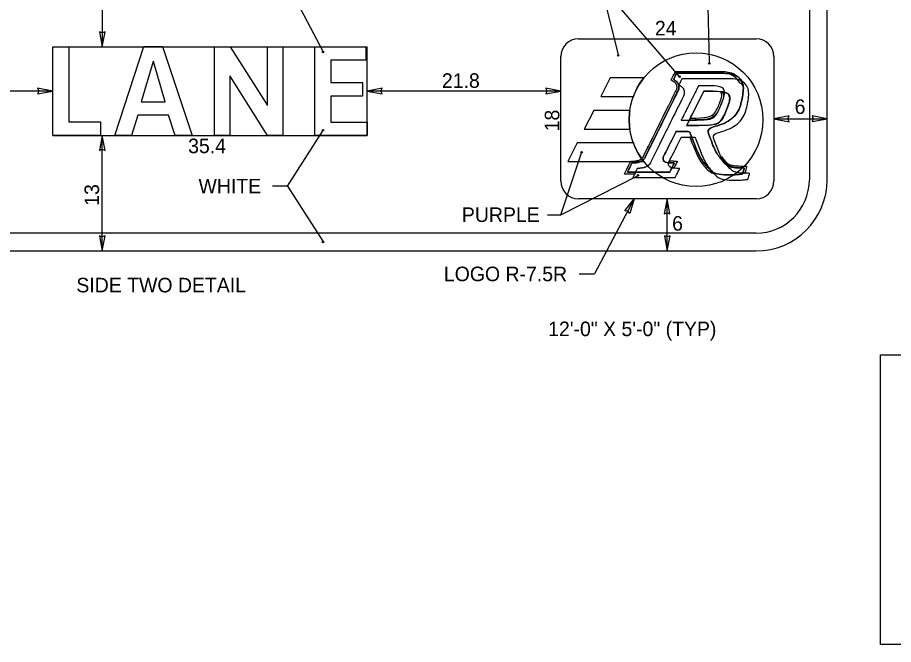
# Model space of a CAD drawing. Extents: x 319706 to 320346, y 1621790 to 1622121.
# Drawn here: x 319772.1 to 319856.4, y 1621813.2 to 1621873.6 of the extents above; entities that cross this region are included whole.
import ezdxf

# ---------------------------------------------------------------- set-up
doc = ezdxf.new("R2010")
doc.units = 0
for name, color, linetype in [('1', 7, 'Continuous'), ('52', 7, 'Continuous'), ('SignPanel', 7, 'Continuous'), ('SOILS_SP83_SHP', 7, 'Continuous'), ('TextAlert', 7, 'Continuous')]:
    doc.layers.add(name, color=color, linetype=linetype)

msp = doc.modelspace()

# ---------------------------------------------------------------- linework, layer by layer
at = {"layer": '1'}
for p, q in [((319798.08, 1621876.744), (319801.479, 1621870.318)), ((319828.244, 1621876.645), (319829.899, 1621869.995)), ((319835.764, 1621867.926), (319828.244, 1621876.645)), ((319838.529, 1621874.588), (319838.662, 1621869.215)), ((319844.895, 1621863.82), (319850.025, 1621863.82)), ((319798.08, 1621857.34), (319801.479, 1621862.649)), ((319824.375, 1621854.589), (319826.382, 1621860.527)), ((319824.375, 1621854.589), (319831.762, 1621858.332)), ((319798.08, 1621857.34), (319796.638, 1621857.34)), ((319798.08, 1621857.34), (319801.479, 1621852.03)), ((319831.44, 1621856.125), (319827.629, 1621848.888)), ((319834.613, 1621851.105), (319834.613, 1621856.125)), ((319823.092, 1621854.589), (319824.375, 1621854.589)), ((319826.132, 1621848.888), (319827.629, 1621848.888))]:
    msp.add_line(p, q, dxfattribs=at)
for centre, major_axis, ratio in [((319801.479, 1621870.248), (0.0736, 0), 0.961364), ((319829.899, 1621869.924), (0, 0.0707), 0.906668), ((319838.662, 1621869.144), (0, 0.0707), 0.906668), ((319835.811, 1621867.877), (0, 0.0707), 0.906668), ((319801.479, 1621862.72), (0.0736, 0), 0.960359), ((319826.382, 1621860.598), (0, 0.0707), 0.906668), ((319831.809, 1621858.381), (0, 0.0707), 0.906668), ((319801.479, 1621851.96), (0.0736, 0), 0.961364)]:
    msp.add_ellipse(centre, major_axis=major_axis, ratio=ratio, dxfattribs=at)
at = {"layer": '52'}
for p, q in [((319780.238, 1621872.088), (319779.968, 1621872.198)), ((319779.968, 1621872.198), (319780.238, 1621870.748)), ((319780.238, 1621870.748), (319780.518, 1621872.198)), ((319780.518, 1621872.198), (319780.238, 1621872.088)), ((319775.465, 1621866.484), (319774.015, 1621866.764)), ((319774.015, 1621866.764), (319774.125, 1621866.484)), ((319807.173, 1621866.754), (319805.723, 1621866.484)), ((319807.063, 1621866.484), (319807.173, 1621866.754)), ((319824.375, 1621866.484), (319822.925, 1621866.764)), ((319822.925, 1621866.764), (319823.035, 1621866.484)), ((319774.125, 1621866.484), (319774.015, 1621866.214)), ((319774.015, 1621866.214), (319775.465, 1621866.484)), ((319805.723, 1621866.484), (319807.173, 1621866.204)), ((319807.173, 1621866.204), (319807.063, 1621866.484)), ((319823.035, 1621866.484), (319822.925, 1621866.214)), ((319822.925, 1621866.214), (319824.375, 1621866.484)), ((319846.345, 1621864.09), (319844.895, 1621863.82)), ((319844.895, 1621863.82), (319846.345, 1621863.54)), ((319846.235, 1621863.82), (319846.345, 1621864.09)), ((319846.345, 1621863.54), (319846.235, 1621863.82)), ((319850.025, 1621863.82), (319848.575, 1621864.1)), ((319848.575, 1621864.1), (319848.685, 1621863.82)), ((319848.685, 1621863.82), (319848.575, 1621863.55)), ((319848.575, 1621863.55), (319850.025, 1621863.82)), ((319780.238, 1621862.22), (319779.958, 1621860.77)), ((319780.508, 1621860.77), (319780.238, 1621862.22)), ((319779.958, 1621860.77), (319780.238, 1621860.88)), ((319780.238, 1621860.88), (319780.508, 1621860.77)), ((319830.526, 1621854.968), (319831.44, 1621856.125)), ((319831.44, 1621856.125), (319831.012, 1621854.712)), ((319834.613, 1621856.125), (319834.333, 1621854.675)), ((319834.883, 1621854.675), (319834.613, 1621856.125)), ((319830.816, 1621854.94), (319830.526, 1621854.968)), ((319831.012, 1621854.712), (319830.816, 1621854.94)), ((319834.333, 1621854.675), (319834.613, 1621854.785)), ((319834.613, 1621854.785), (319834.883, 1621854.675)), ((319780.238, 1621852.445), (319779.968, 1621852.555)), ((319779.968, 1621852.555), (319780.238, 1621851.105)), ((319780.238, 1621851.105), (319780.518, 1621852.555)), ((319780.518, 1621852.555), (319780.238, 1621852.445)), ((319834.613, 1621852.445), (319834.343, 1621852.555)), ((319834.343, 1621852.555), (319834.613, 1621851.105)), ((319834.613, 1621851.105), (319834.893, 1621852.555)), ((319834.893, 1621852.555), (319834.613, 1621852.445))]:
    msp.add_line(p, q, dxfattribs=at)
at = {"layer": 'SignPanel'}
for p, q in [((319848.304, 1621895.565), (319848.304, 1621857.945)), ((319850.014, 1621857.945), (319850.014, 1621895.565)), ((319780.238, 1621882.74), (319780.238, 1621870.748)), ((319826.065, 1621871.514), (319843.183, 1621871.514)), ((319824.375, 1621857.834), (319824.375, 1621869.805)), ((319844.895, 1621869.805), (319844.895, 1621857.834)), ((319775.465, 1621866.484), (319756.605, 1621866.484)), ((319824.375, 1621866.484), (319805.723, 1621866.484)), ((319834.758, 1621865.095), (319834.765, 1621865.11)), ((319834.925, 1621865.03), (319834.918, 1621865.015)), ((319780.238, 1621851.105), (319780.238, 1621862.22)), ((319836.975, 1621862.064), (319836.783, 1621862.064)), ((319831.564, 1621858.674), (319831.474, 1621858.496)), ((319843.183, 1621856.125), (319826.086, 1621856.125)), ((319843.174, 1621852.815), (319733.75, 1621852.815)), ((319733.75, 1621851.105), (319843.174, 1621851.105))]:
    msp.add_line(p, q, dxfattribs=at)
for points in [[(319775.465, 1621862.22), (319775.465, 1621870.748), (319777.011, 1621870.748), (319777.011, 1621863.524), (319780.059, 1621863.524), (319780.059, 1621862.22), (319775.465, 1621862.22)], [(319787.245, 1621862.22), (319786.623, 1621864.169), (319783.673, 1621864.169), (319783.051, 1621862.22), (319781.448, 1621862.22), (319784.244, 1621870.77), (319786.043, 1621870.77), (319788.899, 1621862.22), (319787.245, 1621862.22)], [(319796.151, 1621862.22), (319792.539, 1621867.933), (319792.517, 1621867.933), (319792.517, 1621862.22), (319791.052, 1621862.22), (319791.052, 1621870.748), (319792.539, 1621870.748), (319796.137, 1621865.094), (319796.147, 1621865.094), (319796.151, 1621870.748), (319797.624, 1621870.748), (319797.624, 1621862.22), (319796.151, 1621862.22)], [(319800.714, 1621862.22), (319800.714, 1621870.748), (319805.6, 1621870.748), (319805.6, 1621869.444), (319802.245, 1621869.444), (319802.245, 1621867.297), (319805.278, 1621867.297), (319805.278, 1621865.985), (319802.245, 1621865.985), (319802.245, 1621863.502), (319805.723, 1621863.502), (319805.723, 1621862.22), (319800.714, 1621862.22)], [(319785.165, 1621869.319), (319785.122, 1621869.321), (319783.98, 1621865.451), (319786.307, 1621865.451), (319785.165, 1621869.319)], [(319832.371, 1621867.754), (319829.143, 1621867.754), (319828.232, 1621865.965), (319831.359, 1621865.965)], [(319839.009, 1621866.47), (319838.153, 1621866.47), (319836.491, 1621863.177), (319837.036, 1621863.177)], [(319831.021, 1621864.623), (319827.548, 1621864.623), (319826.636, 1621862.834), (319831.021, 1621862.834)], [(319831.359, 1621861.493), (319825.953, 1621861.493), (319825.042, 1621859.704), (319832.372, 1621859.704)]]:
    msp.add_lwpolyline(points, dxfattribs=at)
msp.add_circle((319837.397, 1621863.729), 6.438, dxfattribs=at)
for centre, radius, start, end in [((319826.084, 1621869.804), 1.71, 90.65967, 180), ((319843.183, 1621869.804), 1.71, 0, 90), ((319837.397, 1621863.729), 6.438, 141.30928, 159.68118), ((319840.633, 1621865.787), 1.786, 44.17508, 57.10952), ((319837.397, 1621863.729), 6.438, 172.01482, 187.98741), ((319837.397, 1621863.729), 6.438, 200.32564, 218.69891), ((319845.493, 1621863.128), 6.357, 207.70861, 215.03564), ((319835.295, 1621859.594), 0.486, 153.95162, 176.84356), ((319835.563, 1621860.105), 1.029, 244.34447, 254.36684), ((319841.02, 1621860.665), 2.825, 217.43245, 229.81517), ((319842.449, 1621863.158), 4.583, 263.2057, 265.47819), ((319826.084, 1621857.835), 1.71, 180, 270), ((319843.174, 1621857.945), 6.84, 270, 0), ((319843.174, 1621857.945), 5.13, 270, 0), ((319843.183, 1621857.835), 1.71, 270, 360)]:
    msp.add_arc(centre, radius, start, end, dxfattribs=at)
for points, degree in [([(319834.765, 1621865.11), (319835.228, 1621866.043), (319835.557, 1621866.705), (319835.557, 1621866.705), (319835.557, 1621866.705), (319835.564, 1621866.76), (319835.564, 1621866.76), (319835.564, 1621866.76), (319835.564, 1621866.839), (319835.564, 1621866.839), (319835.564, 1621866.839), (319835.564, 1621866.899), (319835.564, 1621866.899), (319835.564, 1621866.899), (319835.559, 1621866.963), (319835.559, 1621866.963), (319835.559, 1621866.963), (319835.541, 1621867.04), (319835.541, 1621867.04), (319835.541, 1621867.04), (319835.509, 1621867.123), (319835.509, 1621867.123), (319835.509, 1621867.123), (319835.479, 1621867.173), (319835.479, 1621867.173), (319835.479, 1621867.173), (319835.419, 1621867.252), (319835.419, 1621867.252), (319835.419, 1621867.252), (319835.331, 1621867.325), (319835.331, 1621867.325), (319835.331, 1621867.325), (319835.234, 1621867.396), (319835.234, 1621867.396), (319835.234, 1621867.396), (319834.99, 1621867.544), (319834.99, 1621867.544), (319834.99, 1621867.544), (319835.41, 1621868.375), (319835.41, 1621868.375), (319835.41, 1621868.375), (319839.531, 1621868.375), (319839.531, 1621868.375), (319840.818, 1621868.375), (319841.612, 1621867.814), (319841.914, 1621867.032)], 3), ([(319835.461, 1621862.583), (319835.461, 1621862.583), (319834.368, 1621860.376), (319834.368, 1621860.376), (319834.17, 1621860.054), (319834.313, 1621859.567), (319835.312, 1621859.567), (319835.312, 1621859.567), (319834.866, 1621858.674), (319834.866, 1621858.674), (319834.866, 1621858.674), (319830.786, 1621858.674), (319830.786, 1621858.674), (319830.786, 1621858.674), (319831.232, 1621859.567), (319831.232, 1621859.567), (319831.232, 1621859.567), (319831.359, 1621859.567), (319831.359, 1621859.567), (319831.359, 1621859.567), (319831.497, 1621859.573), (319831.497, 1621859.573), (319831.497, 1621859.573), (319831.612, 1621859.585), (319831.612, 1621859.585), (319831.612, 1621859.585), (319831.811, 1621859.627), (319831.811, 1621859.627), (319831.811, 1621859.627), (319831.962, 1621859.669), (319831.962, 1621859.669), (319831.962, 1621859.669), (319832.088, 1621859.724), (319832.088, 1621859.724), (319832.088, 1621859.724), (319832.179, 1621859.772), (319832.179, 1621859.772), (319832.179, 1621859.772), (319832.269, 1621859.826), (319832.269, 1621859.826), (319832.269, 1621859.826), (319832.36, 1621859.911), (319832.36, 1621859.911), (319832.36, 1621859.911), (319832.426, 1621859.995), (319832.426, 1621859.995), (319832.426, 1621859.995), (319832.45, 1621860.043), (319832.45, 1621860.043), (319832.45, 1621860.043), (319835.731, 1621866.653), (319835.731, 1621866.653), (319835.731, 1621866.653), (319835.743, 1621866.749), (319835.743, 1621866.749), (319835.743, 1621866.749), (319835.743, 1621866.839), (319835.743, 1621866.839), (319835.743, 1621866.839), (319835.743, 1621866.906), (319835.743, 1621866.906), (319835.743, 1621866.906), (319835.737, 1621866.99), (319835.737, 1621866.99), (319835.737, 1621866.99), (319835.712, 1621867.093), (319835.712, 1621867.093), (319835.712, 1621867.093), (319835.67, 1621867.201), (319835.67, 1621867.201), (319835.67, 1621867.201), (319835.628, 1621867.273), (319835.628, 1621867.273), (319835.628, 1621867.273), (319835.549, 1621867.376), (319835.549, 1621867.376), (319835.549, 1621867.376), (319835.441, 1621867.467), (319835.441, 1621867.467), (319835.441, 1621867.467), (319835.333, 1621867.545), (319835.333, 1621867.545), (319835.333, 1621867.545), (319835.224, 1621867.611), (319835.224, 1621867.611), (319835.224, 1621867.611), (319835.52, 1621868.196), (319835.52, 1621868.196), (319835.52, 1621868.196), (319839.531, 1621868.196), (319839.531, 1621868.196), (319841.352, 1621868.196), (319842.082, 1621867.092), (319841.827, 1621865.8), (319841.544, 1621864.369), (319840.171, 1621863.249), (319838.302, 1621862.922), (319838.711, 1621862.159), (319839.2, 1621860.697), (319839.899, 1621859.826), (319840.374, 1621859.234), (319841.201, 1621859.09), (319842.045, 1621859.09), (319842.045, 1621859.09), (319841.882, 1621858.519), (319841.882, 1621858.519), (319841.882, 1621858.519), (319841.77, 1621858.503), (319841.77, 1621858.503), (319841.306, 1621858.441), (319841.008, 1621858.425), (319840.665, 1621858.425), (319839.529, 1621858.425), (319838.831, 1621858.752), (319838.295, 1621859.421), (319837.67, 1621860.199), (319837.067, 1621861.856), (319836.766, 1621862.583), (319836.766, 1621862.583), (319835.461, 1621862.583), (319835.461, 1621862.583)], 3), ([(319835.98, 1621862.064), (319835.98, 1621862.064), (319834.887, 1621859.858), (319834.887, 1621859.858), (319834.688, 1621859.536), (319834.831, 1621859.048), (319835.831, 1621859.048), (319835.831, 1621859.048), (319835.385, 1621858.156), (319835.385, 1621858.156), (319835.385, 1621858.156), (319831.304, 1621858.156), (319831.304, 1621858.156), (319831.304, 1621858.156), (319831.751, 1621859.048), (319831.751, 1621859.048), (319831.751, 1621859.048), (319831.877, 1621859.048), (319831.877, 1621859.048), (319831.877, 1621859.048), (319832.016, 1621859.055), (319832.016, 1621859.055), (319832.016, 1621859.055), (319832.13, 1621859.066), (319832.13, 1621859.066), (319832.13, 1621859.066), (319832.33, 1621859.108), (319832.33, 1621859.108), (319832.33, 1621859.108), (319832.48, 1621859.151), (319832.48, 1621859.151), (319832.48, 1621859.151), (319832.607, 1621859.205), (319832.607, 1621859.205), (319832.607, 1621859.205), (319832.697, 1621859.253), (319832.697, 1621859.253), (319832.697, 1621859.253), (319832.788, 1621859.308), (319832.788, 1621859.308), (319832.788, 1621859.308), (319832.878, 1621859.392), (319832.878, 1621859.392), (319832.878, 1621859.392), (319832.945, 1621859.476), (319832.945, 1621859.476), (319832.945, 1621859.476), (319832.968, 1621859.525), (319832.968, 1621859.525), (319832.968, 1621859.525), (319836.249, 1621866.134), (319836.249, 1621866.134), (319836.249, 1621866.134), (319836.261, 1621866.23), (319836.261, 1621866.23), (319836.261, 1621866.23), (319836.261, 1621866.32), (319836.261, 1621866.32), (319836.261, 1621866.32), (319836.261, 1621866.387), (319836.261, 1621866.387), (319836.261, 1621866.387), (319836.255, 1621866.471), (319836.255, 1621866.471), (319836.255, 1621866.471), (319836.231, 1621866.574), (319836.231, 1621866.574), (319836.231, 1621866.574), (319836.189, 1621866.683), (319836.189, 1621866.683), (319836.189, 1621866.683), (319836.147, 1621866.755), (319836.147, 1621866.755), (319836.147, 1621866.755), (319836.068, 1621866.858), (319836.068, 1621866.858), (319836.068, 1621866.858), (319835.96, 1621866.948), (319835.96, 1621866.948), (319835.96, 1621866.948), (319835.851, 1621867.026), (319835.851, 1621867.026), (319835.851, 1621867.026), (319835.743, 1621867.092), (319835.743, 1621867.092), (319835.743, 1621867.092), (319836.038, 1621867.678), (319836.038, 1621867.678), (319836.038, 1621867.678), (319840.05, 1621867.678), (319840.05, 1621867.678), (319841.87, 1621867.678), (319842.601, 1621866.573), (319842.346, 1621865.281), (319842.063, 1621863.85), (319840.69, 1621862.73), (319838.821, 1621862.403), (319839.23, 1621861.641), (319839.719, 1621860.178), (319840.418, 1621859.307), (319840.893, 1621858.716), (319841.72, 1621858.571), (319842.564, 1621858.571), (319842.564, 1621858.571), (319842.4, 1621858), (319842.4, 1621858), (319842.4, 1621858), (319842.288, 1621857.984), (319842.288, 1621857.984), (319841.825, 1621857.922), (319841.526, 1621857.907), (319841.184, 1621857.907), (319840.048, 1621857.907), (319839.35, 1621858.233), (319838.813, 1621858.902), (319838.189, 1621859.68), (319837.586, 1621861.338), (319837.285, 1621862.064), (319837.285, 1621862.064), (319835.98, 1621862.064), (319835.98, 1621862.064)], 3), ([(319834.925, 1621865.03), (319835.388, 1621865.963), (319835.731, 1621866.653), (319835.731, 1621866.653), (319835.731, 1621866.653), (319835.743, 1621866.749), (319835.743, 1621866.749), (319835.743, 1621866.749), (319835.743, 1621866.839), (319835.743, 1621866.839), (319835.743, 1621866.839), (319835.743, 1621866.906), (319835.743, 1621866.906), (319835.743, 1621866.906), (319835.737, 1621866.99), (319835.737, 1621866.99), (319835.737, 1621866.99), (319835.712, 1621867.093), (319835.712, 1621867.093), (319835.712, 1621867.093), (319835.67, 1621867.201), (319835.67, 1621867.201), (319835.67, 1621867.201), (319835.628, 1621867.273), (319835.628, 1621867.273), (319835.628, 1621867.273), (319835.549, 1621867.376), (319835.549, 1621867.376), (319835.549, 1621867.376), (319835.441, 1621867.467), (319835.441, 1621867.467), (319835.441, 1621867.467), (319835.333, 1621867.545), (319835.333, 1621867.545), (319835.333, 1621867.545), (319835.224, 1621867.611), (319835.224, 1621867.611), (319835.224, 1621867.611), (319835.52, 1621868.196), (319835.52, 1621868.196), (319835.52, 1621868.196), (319839.531, 1621868.196), (319839.531, 1621868.196), (319841.352, 1621868.196), (319842.082, 1621867.092), (319841.827, 1621865.8), (319841.544, 1621864.369), (319840.171, 1621863.249), (319838.302, 1621862.922), (319838.711, 1621862.159), (319839.2, 1621860.697), (319839.899, 1621859.826), (319840.374, 1621859.234), (319841.201, 1621859.09), (319842.045, 1621859.09), (319842.045, 1621859.09), (319841.882, 1621858.519), (319841.882, 1621858.519), (319841.882, 1621858.519), (319841.77, 1621858.503), (319841.77, 1621858.503), (319841.306, 1621858.441), (319841.008, 1621858.425), (319840.665, 1621858.425), (319839.529, 1621858.425), (319838.831, 1621858.752), (319838.295, 1621859.421), (319837.67, 1621860.199), (319837.067, 1621861.856), (319836.766, 1621862.583), (319836.766, 1621862.583), (319835.461, 1621862.583), (319835.461, 1621862.583)], 3), ([(319841.603, 1621867.287), (319841.254, 1621867.836), (319840.57, 1621868.196), (319839.531, 1621868.196), (319839.531, 1621868.196), (319835.52, 1621868.196), (319835.52, 1621868.196), (319835.52, 1621868.196), (319835.224, 1621867.611), (319835.224, 1621867.611), (319835.224, 1621867.611), (319835.333, 1621867.545), (319835.333, 1621867.545), (319835.333, 1621867.545), (319835.441, 1621867.467), (319835.441, 1621867.467), (319835.441, 1621867.467), (319835.549, 1621867.376), (319835.549, 1621867.376), (319835.549, 1621867.376), (319835.628, 1621867.273), (319835.628, 1621867.273), (319835.628, 1621867.273), (319835.67, 1621867.201), (319835.67, 1621867.201), (319835.67, 1621867.201), (319835.712, 1621867.093), (319835.712, 1621867.093), (319835.712, 1621867.093), (319835.737, 1621866.99), (319835.737, 1621866.99), (319835.737, 1621866.99), (319835.743, 1621866.906), (319835.743, 1621866.906), (319835.743, 1621866.906), (319835.743, 1621866.839), (319835.743, 1621866.839), (319835.743, 1621866.839), (319835.743, 1621866.749), (319835.743, 1621866.749), (319835.743, 1621866.749), (319835.731, 1621866.653), (319835.731, 1621866.653), (319835.731, 1621866.653), (319835.388, 1621865.963), (319834.925, 1621865.03)], 3), ([(319836.294, 1621864.332), (319836.104, 1621863.957), (319835.972, 1621863.696), (319835.972, 1621863.696), (319835.972, 1621863.696), (319836.517, 1621863.696), (319836.517, 1621863.696), (319838.306, 1621863.696), (319839.272, 1621863.828), (319839.873, 1621865.384), (319840.29, 1621866.462), (319839.828, 1621866.988), (319838.49, 1621866.988), (319838.49, 1621866.988), (319837.634, 1621866.988), (319837.634, 1621866.988)], 3), ([(319837.634, 1621866.988), (319837.634, 1621866.988), (319836.785, 1621865.307), (319836.301, 1621864.347)], 2), ([(319838.153, 1621866.47), (319838.153, 1621866.47), (319836.491, 1621863.177), (319836.491, 1621863.177), (319836.491, 1621863.177), (319837.036, 1621863.177), (319837.036, 1621863.177), (319838.825, 1621863.177), (319839.79, 1621863.309), (319840.392, 1621864.865), (319840.809, 1621865.943), (319840.347, 1621866.47), (319839.009, 1621866.47), (319839.009, 1621866.47), (319838.153, 1621866.47), (319838.153, 1621866.47)], 3), ([(319839.985, 1621866.323), (319840.058, 1621866.079), (319840.021, 1621865.766), (319839.873, 1621865.384), (319839.299, 1621863.898), (319838.392, 1621863.711), (319836.753, 1621863.697)], 3), ([(319836.844, 1621863.877), (319838.401, 1621863.895), (319839.179, 1621864.083), (319839.706, 1621865.448), (319839.867, 1621865.863), (319839.898, 1621866.171), (319839.786, 1621866.388)], 3), ([(319837.036, 1621863.177), (319838.825, 1621863.177), (319839.79, 1621863.309), (319840.392, 1621864.865), (319840.809, 1621865.943), (319840.347, 1621866.47), (319839.009, 1621866.47)], 3), ([(319839.786, 1621866.388), (319839.857, 1621866.369), (319839.924, 1621866.348), (319839.985, 1621866.323)], 2), ([(319831.474, 1621858.496), (319830.904, 1621858.496), (319830.496, 1621858.496), (319830.496, 1621858.496), (319830.496, 1621858.496), (319831.121, 1621859.746), (319831.121, 1621859.746), (319831.121, 1621859.746), (319831.355, 1621859.746), (319831.355, 1621859.746), (319831.355, 1621859.746), (319831.484, 1621859.752), (319831.484, 1621859.752), (319831.484, 1621859.752), (319831.584, 1621859.762), (319831.584, 1621859.762), (319831.584, 1621859.762), (319831.768, 1621859.801), (319831.768, 1621859.801), (319831.768, 1621859.801), (319831.902, 1621859.838), (319831.902, 1621859.838), (319831.902, 1621859.838), (319832.01, 1621859.885), (319832.01, 1621859.885), (319832.01, 1621859.885), (319832.091, 1621859.928), (319832.091, 1621859.928), (319832.091, 1621859.928), (319832.161, 1621859.97), (319832.161, 1621859.97), (319832.161, 1621859.97), (319832.228, 1621860.032), (319832.228, 1621860.032), (319832.228, 1621860.032), (319832.274, 1621860.091), (319832.274, 1621860.091), (319832.274, 1621860.091), (319832.289, 1621860.122), (319832.289, 1621860.122), (319832.289, 1621860.122), (319833.786, 1621863.137), (319834.758, 1621865.095)], 3), ([(319835.461, 1621862.583), (319835.461, 1621862.583), (319834.368, 1621860.376), (319834.368, 1621860.376), (319834.17, 1621860.054), (319834.313, 1621859.567), (319835.312, 1621859.567), (319835.312, 1621859.567), (319834.866, 1621858.674), (319834.866, 1621858.674), (319834.866, 1621858.674), (319830.786, 1621858.674), (319830.786, 1621858.674), (319830.786, 1621858.674), (319831.232, 1621859.567), (319831.232, 1621859.567), (319831.232, 1621859.567), (319831.359, 1621859.567), (319831.359, 1621859.567), (319831.359, 1621859.567), (319831.497, 1621859.573), (319831.497, 1621859.573), (319831.497, 1621859.573), (319831.612, 1621859.585), (319831.612, 1621859.585), (319831.612, 1621859.585), (319831.811, 1621859.627), (319831.811, 1621859.627), (319831.811, 1621859.627), (319831.962, 1621859.669), (319831.962, 1621859.669), (319831.962, 1621859.669), (319832.088, 1621859.724), (319832.088, 1621859.724), (319832.088, 1621859.724), (319832.179, 1621859.772), (319832.179, 1621859.772), (319832.179, 1621859.772), (319832.269, 1621859.826), (319832.269, 1621859.826), (319832.269, 1621859.826), (319832.36, 1621859.911), (319832.36, 1621859.911), (319832.36, 1621859.911), (319832.426, 1621859.995), (319832.426, 1621859.995), (319832.426, 1621859.995), (319832.45, 1621860.043), (319832.45, 1621860.043), (319832.45, 1621860.043), (319833.946, 1621863.058), (319834.918, 1621865.015)], 3), ([(319834.918, 1621865.015), (319833.946, 1621863.058), (319832.45, 1621860.043), (319832.45, 1621860.043), (319832.45, 1621860.043), (319832.426, 1621859.995), (319832.426, 1621859.995), (319832.426, 1621859.995), (319832.36, 1621859.911), (319832.36, 1621859.911), (319832.36, 1621859.911), (319832.269, 1621859.826), (319832.269, 1621859.826), (319832.269, 1621859.826), (319832.179, 1621859.772), (319832.179, 1621859.772), (319832.179, 1621859.772), (319832.088, 1621859.724), (319832.088, 1621859.724), (319832.088, 1621859.724), (319831.962, 1621859.669), (319831.962, 1621859.669), (319831.962, 1621859.669), (319831.811, 1621859.627), (319831.811, 1621859.627), (319831.811, 1621859.627), (319831.612, 1621859.585), (319831.612, 1621859.585), (319831.612, 1621859.585), (319831.497, 1621859.573), (319831.497, 1621859.573), (319831.497, 1621859.573), (319831.359, 1621859.567), (319831.359, 1621859.567), (319831.359, 1621859.567), (319831.232, 1621859.567), (319831.232, 1621859.567), (319831.232, 1621859.567), (319830.786, 1621858.674), (319830.786, 1621858.674), (319830.786, 1621858.674), (319831.104, 1621858.674), (319831.564, 1621858.674)], 3), ([(319836.753, 1621863.697), (319836.782, 1621863.754), (319836.812, 1621863.814), (319836.844, 1621863.877)], 2), ([(319836.783, 1621862.064), (319837.084, 1621861.308), (319837.609, 1621859.99), (319838.155, 1621859.309), (319838.44, 1621858.954), (319838.779, 1621858.685), (319839.197, 1621858.507)], 3), ([(319838.777, 1621858.949), (319838.6, 1621859.081), (319838.442, 1621859.238), (319838.295, 1621859.421), (319837.792, 1621860.047), (319837.304, 1621861.242), (319836.975, 1621862.064)], 3), ([(319839.865, 1621860.172), (319839.922, 1621860.09), (319839.98, 1621860.012), (319840.039, 1621859.938), (319840.471, 1621859.399), (319841.217, 1621859.269), (319842.282, 1621859.269), (319842.282, 1621859.269), (319842.165, 1621858.859), (319842.088, 1621858.589)], 3), ([(319835.117, 1621859.177), (319835.219, 1621859.38), (319835.312, 1621859.567), (319835.312, 1621859.567), (319835.112, 1621859.567), (319834.946, 1621859.587), (319834.81, 1621859.62)], 3), ([(319834.859, 1621859.807), (319835.033, 1621859.769), (319835.274, 1621859.746), (319835.602, 1621859.746), (319835.602, 1621859.746), (319835.443, 1621859.428), (319835.285, 1621859.113)], 3), ([(319841.907, 1621858.607), (319841.953, 1621858.767), (319842.045, 1621859.09), (319842.045, 1621859.09), (319841.4, 1621859.09), (319840.764, 1621859.174), (319840.288, 1621859.479)], 3)]:
    msp.add_open_spline(points, degree=degree, dxfattribs=at)
at = {"layer": 'SOILS_SP83_SHP'}
for p, q in [((319775.465, 1621870.748), (319805.723, 1621870.748)), ((319775.465, 1621862.22), (319775.465, 1621870.708)), ((319805.723, 1621862.22), (319805.723, 1621870.748)), ((319775.465, 1621862.22), (319805.723, 1621862.22))]:
    msp.add_line(p, q, dxfattribs=at)
at = {"layer": 'TextAlert'}
msp.add_lwpolyline([(319855.135, 1621841.105), (319915.823, 1621841.105), (319915.823, 1621813.24), (319855.135, 1621813.24)], close=True, dxfattribs=at)

# ---------------------------------------------------------------- texts
at = {"layer": '1'}
for s, p in [('24', (319833.436, 1621871.834)), ('21.8', (319812.933, 1621866.794)), ('6', (319846.887, 1621864.285)), ('35.4', (319788.502, 1621860.51)), ('WHITE', (319789.502, 1621856.64)), ('PURPLE', (319814.854, 1621853.889)), ('6', (319835.091, 1621853.057)), ('LOGO R-7.5R', (319813.123, 1621848.191)), ('SIDE TWO DETAIL', (319777.743, 1621847.118)), ('12\'-0" X 5\'-0" (TYP)', (319823.161, 1621842.905))]:
    msp.add_text(s, height=1.4, dxfattribs=at).set_placement(p)
for s, p in [('18', (319824.234, 1621862.608)), ('13', (319779.928, 1621855.446))]:
    msp.add_text(s, height=1.4, rotation=90, dxfattribs=at).set_placement(p)

doc.saveas('drawing.dxf')
